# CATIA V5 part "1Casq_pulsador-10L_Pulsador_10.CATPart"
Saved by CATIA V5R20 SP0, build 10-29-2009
Part number: 1Casq_pulsador-10L_Pulsador_10
Revision: ANY
Definition: UNKNOWN
Nomenclature: 1Casq_pulsador-10L_Pulsador_10
Source: Unknown
Bounding box of the stored display mesh (mm): x -8.8 to 8.8, y 0 to 15.3, z -8.8 to 8.8
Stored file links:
  C:\Users\Utente\Desktop\IO LAVORO\3D X SITO CF\CUMSA\3D files BA\BA 101822\1Casq_pulsador-10L_Pulsador_10.CATPart
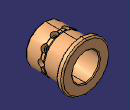
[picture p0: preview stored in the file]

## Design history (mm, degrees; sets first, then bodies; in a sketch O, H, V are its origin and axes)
Body1 "MatrizC1" (main body)
  Solid1: solid without history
